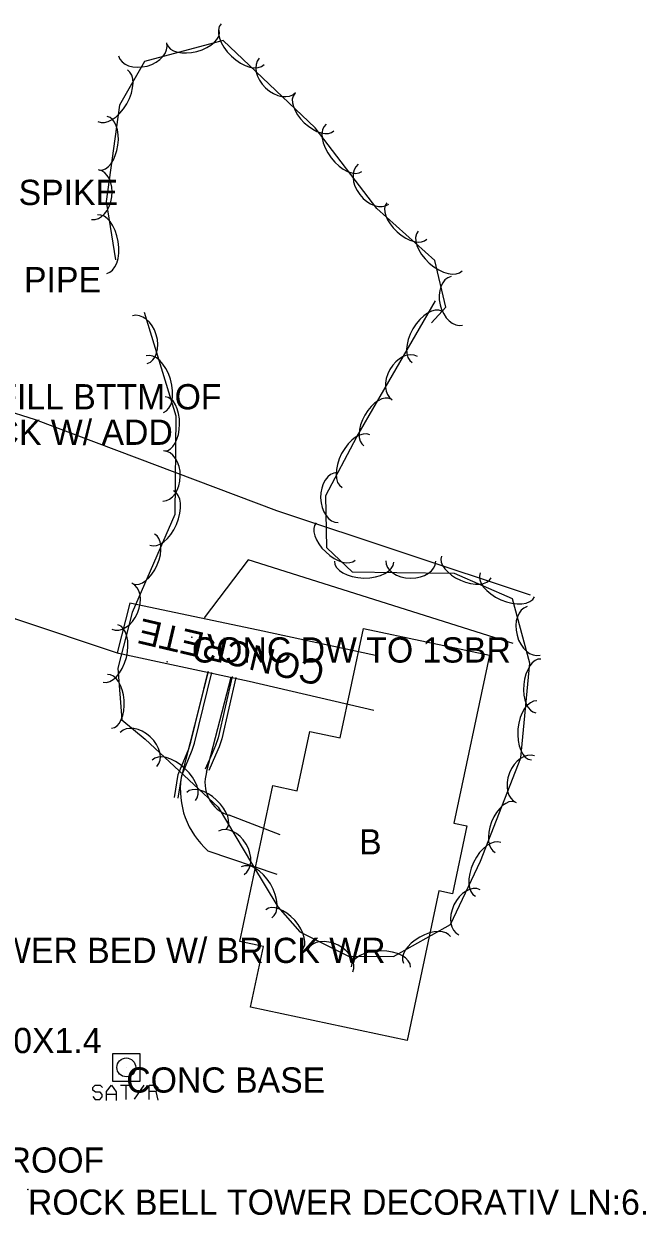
# Model space of a CAD drawing. Extents: x 954793 to 988390, y 1867850 to 1924428.
# Drawn here: x 961195.8 to 961319, y 1905785.4 to 1906021.4 of the extents above; entities that cross this region are included whole.
import ezdxf

# ---------------------------------------------------------------- set-up
doc = ezdxf.new("R2010")
doc.units = 0
for name, color, linetype in [('S_BUILDING', 7, 'Continuous'), ('S_BUILDING_ANNOT', 7, 'Continuous'), ('S_DRIVEWAY', 7, 'Continuous'), ('S_DRIVEWAY_ANNOT', 7, 'Continuous'), ('S_GRD_PT_SYM', 7, 'Continuous'), ('S_MISC_STRUCTURES_ANNOT', 7, 'Continuous'), ('S_MSC_PT_SYM', 7, 'Continuous'), ('S_PHOTO_IRON_PIN', 7, 'Continuous'), ('S_SATELLITE_RECEIVER', 7, 'Continuous'), ('S_SATELLITE_RECEIVER_ANNOT', 7, 'Continuous'), ('S_SECONDARY_CTL_ANNOT', 7, 'Continuous'), ('S_SIDE_DRAIN_ANNOT', 7, 'Continuous'), ('S_SIDEWALK', 7, 'Continuous'), ('S_SURVEY_TEXT_ANNOT', 7, 'Continuous'), ('S_TREE', 7, 'Continuous'), ('S_WATER_UTILITIES_ANNOT', 7, 'Continuous')]:
    doc.layers.add(name, color=color, linetype=linetype)

msp = doc.modelspace()

# ---------------------------------------------------------------- linework, layer by layer
at = {"layer": 'S_BUILDING'}
msp.add_lwpolyline([(961277.98, 1905849.64), (961271.68, 1905820.06), (961240.71, 1905826.65), (961243.26, 1905838.64), (961238.56, 1905839.64), (961245.13, 1905870.5), (961249.92, 1905869.47), (961252.43, 1905881.23), (961258.43, 1905879.96), (961263.04, 1905901.63), (961288, 1905896.31), (961280.92, 1905863.06), (961283.51, 1905862.51), (961280.64, 1905849.07)], close=True, dxfattribs=at)
at = {"layer": 'S_DRIVEWAY'}
for points in [[(961296.1, 1905908.22), (961245.91, 1905924.92), (961198.1, 1905942.95), (961151.44, 1905957.69), (961122.09, 1905969.17)], [(961117.43, 1905954.73), (961136.52, 1905950.69), (961174.2, 1905937.04), (961189.27, 1905931.84), (961190.7, 1905910.59), (961190.9, 1905906.51), (961191.87, 1905904.94), (961194.15, 1905903.56), (961214.46, 1905896.76)], [(961292.67, 1905898.66), (961240.24, 1905915.2), (961231.54, 1905903.74)], [(961265.41, 1905896.28), (961242.23, 1905901.3), (961216.78, 1905906.66), (961214.32, 1905896.78), (961240.4, 1905891.19), (961265.07, 1905885.47)]]:
    msp.add_lwpolyline(points, dxfattribs=at)
at = {"layer": 'S_GRD_PT_SYM'}
msp.add_lwpolyline([(961224.17, 1905895.04), (961224.17, 1905895.09), (961224.17, 1905895.04), (961224.12, 1905895.04), (961224.17, 1905895.04), (961224.17, 1905894.99), (961224.17, 1905895.04), (961224.22, 1905895.04)], dxfattribs=at)
at = {"layer": 'S_MSC_PT_SYM'}
for points in [[(961229.06, 1905899.87), (961229.06, 1905899.92), (961229.06, 1905899.87), (961229.01, 1905899.87), (961229.06, 1905899.87), (961229.06, 1905899.82), (961229.06, 1905899.87), (961229.11, 1905899.87)], [(961229.06, 1905899.87), (961229.06, 1905899.92), (961229.06, 1905899.87), (961229.01, 1905899.87), (961229.06, 1905899.87), (961229.06, 1905899.82), (961229.06, 1905899.87), (961229.11, 1905899.87)], [(961196.63, 1905790.52), (961196.63, 1905790.57), (961196.63, 1905790.52), (961196.58, 1905790.52), (961196.63, 1905790.52), (961196.63, 1905790.47), (961196.63, 1905790.52), (961196.68, 1905790.52)], [(961196.63, 1905790.52), (961196.63, 1905790.57), (961196.63, 1905790.52), (961196.58, 1905790.52), (961196.63, 1905790.52), (961196.63, 1905790.47), (961196.63, 1905790.52), (961196.68, 1905790.52)]]:
    msp.add_lwpolyline(points, close=True, dxfattribs=at)
for points in [[(961229.06, 1905899.87), (961229.06, 1905899.92), (961229.06, 1905899.87), (961229.01, 1905899.87), (961229.06, 1905899.87), (961229.06, 1905899.82), (961229.06, 1905899.87), (961229.11, 1905899.87)], [(961196.63, 1905790.52), (961196.63, 1905790.57), (961196.63, 1905790.52), (961196.58, 1905790.52), (961196.63, 1905790.52), (961196.63, 1905790.47), (961196.63, 1905790.52), (961196.68, 1905790.52)]]:
    msp.add_lwpolyline(points, dxfattribs=at)
at = {"layer": 'S_PHOTO_IRON_PIN'}
msp.add_line((961216.09, 1905814.71), (961216.09, 1905814.71), dxfattribs=at)
at = {"layer": 'S_SATELLITE_RECEIVER'}
for p, q in [((961209.47, 1905810.72), (961209.94, 1905811.19)), ((961209.47, 1905810.18), (961209.47, 1905810.72)), ((961209.94, 1905811.19), (961210.95, 1905811.19)), ((961210.95, 1905811.19), (961211.41, 1905810.72)), ((961212.19, 1905809.95), (961213.19, 1905811.19)), ((961213.19, 1905811.19), (961214.12, 1905809.87)), ((961214.98, 1905811.19), (961216.91, 1905811.19)), ((961215.98, 1905811.19), (961215.98, 1905808.32)), ((961217.69, 1905808.4), (961219.63, 1905811.19)), ((961220.63, 1905808.32), (961220.63, 1905811.19)), ((961220.63, 1905811.19), (961221.87, 1905811.19)), ((961221.87, 1905811.19), (961222.34, 1905810.72)), ((961222.34, 1905810.72), (961222.34, 1905810.33)), ((961210.02, 1905809.79), (961209.47, 1905810.18)), ((961209.47, 1905808.94), (961209.94, 1905808.32)), ((961209.94, 1905808.32), (961210.87, 1905808.32)), ((961210.95, 1905809.79), (961210.02, 1905809.79)), ((961210.87, 1905808.32), (961211.33, 1905808.86)), ((961211.33, 1905809.33), (961210.95, 1905809.79)), ((961211.33, 1905808.86), (961211.33, 1905809.33)), ((961212.19, 1905808.16), (961212.19, 1905809.95)), ((961214.05, 1905809.33), (961212.19, 1905809.33)), ((961214.12, 1905809.87), (961214.12, 1905808.16)), ((961221.95, 1905809.95), (961220.63, 1905809.95)), ((961222.34, 1905810.33), (961221.95, 1905809.95)), ((961221.95, 1905809.95), (961222.34, 1905808.24))]:
    msp.add_line(p, q, dxfattribs=at)
msp.add_lwpolyline([(961213.43, 1905811.94), (961213.43, 1905817.45), (961218.77, 1905817.45), (961218.77, 1905811.94)], close=True, dxfattribs=at)
msp.add_circle((961216.09, 1905814.71), 1.86, dxfattribs=at)
at = {"layer": 'S_SIDEWALK'}
for points in [[(961225.63, 1905868.14), (961226.35, 1905872.71), (961228.45, 1905877.81), (961228.86, 1905879.09), (961232.3, 1905893.1)], [(961226.37, 1905868.02), (961227.07, 1905872.5), (961229.16, 1905877.55), (961229.59, 1905878.88), (961233.03, 1905892.92)], [(961232.29, 1905893.07), (961226.95, 1905872.11)], [(961237.05, 1905892.1), (961234.26, 1905879.97), (961233.76, 1905878.43), (961233.09, 1905876.86), (961231.72, 1905873.79)], [(961232, 1905873.15), (961236.84, 1905892)], [(961237.78, 1905891.93), (961234.99, 1905879.77), (961234.47, 1905878.16), (961233.78, 1905876.56), (961232.41, 1905873.48)], [(961246.53, 1905860.76), (961236.47, 1905864.63)], [(961232.26, 1905857.58), (961245.87, 1905852.95)]]:
    msp.add_lwpolyline(points, dxfattribs=at)
msp.add_arc((961242.98, 1905869.73), 16.2, 171.5701, 228.5649, dxfattribs=at)
msp.add_ellipse((961238.34, 1905871.04), major_axis=(0.96, -6.61), ratio=0.999923, start_param=4.247433, end_param=5.854421, dxfattribs=at)
at = {"layer": 'S_TREE'}
for points in [[(961276.49, 1905962.13), (961279.37, 1905965.26), (961277.18, 1905974.46), (961265.68, 1905984.8), (961253.51, 1906000.75), (961235.24, 1906018.06), (961219.73, 1906013.92), (961214.76, 1906005.25), (961212.1, 1905986.15), (961213.94, 1905974.63)], [(961219.61, 1905964.23), (961225.9, 1905943.72), (961225.69, 1905924.19), (961217.26, 1905904.76), (961214.42, 1905893.76), (961215.18, 1905883.54), (961219.86, 1905879.68), (961234.31, 1905866.27), (961241.07, 1905854.81), (961246.08, 1905846.47), (961250.44, 1905841.56), (961260.08, 1905836.74), (961269, 1905836.69), (961280.26, 1905843.03), (961286.19, 1905855.57), (961294.18, 1905876), (961295.95, 1905894.74), (961292.57, 1905907.49), (961281.09, 1905912.51), (961269.65, 1905912.62), (961260.9, 1905912.76), (961255.79, 1905917.61), (961255.57, 1905927.92), (961261.72, 1905939.58), (961277.33, 1905966.48)]]:
    msp.add_lwpolyline(points, dxfattribs=at)
for centre, major_axis, ratio in [((961239.11, 1906017.31), (4.26, -4.04), 0.55008), ((961229.34, 1906018.69), (5.17, 1.38), 0.540699), ((961219.32, 1906016.28), (4.79, 1.28), 0.685311), ((961246.01, 1906011.14), (3.6, -3.41), 0.685311), ((961213.39, 1906007.13), (2.92, 5.09), 0.55008), ((961253.31, 1906003.86), (3.88, -3.68), 0.540699), ((961211.57, 1905997.7), (0.74, 5.3), 0.540699), ((961259.19, 1905996.8), (3.56, -4.66), 0.55008), ((961209.89, 1905987.53), (0.68, 4.91), 0.685311), ((961265.02, 1905989.6), (3.01, -3.94), 0.685311), ((961271.63, 1905982.31), (3.98, -3.58), 0.540699), ((961211.3, 1905977.72), (-0.93, 5.79), 0.55008), ((961278.22, 1905976.38), (4.36, -3.92), 0.55008), ((961281.52, 1905966.5), (1.15, -4.82), 0.685311), ((961218.78, 1905958.8), (-1.45, 4.74), 0.685311), ((961275.64, 1905959.35), (-2.94, -5.08), 0.55008), ((961221.75, 1905950.02), (-1.72, 5.61), 0.55008), ((961271.22, 1905951.21), (-2.49, -4.29), 0.685311), ((961223.76, 1905942.12), (0.06, 5.35), 0.540699), ((961265.82, 1905942.43), (-2.68, -4.62), 0.540699), ((961261.57, 1905934.75), (-2.74, -5.19), 0.55008), ((961223.39, 1905931.82), (0.05, 4.96), 0.685311), ((961257.96, 1905927.55), (0.1, -4.95), 0.685311), ((961223.08, 1905923.51), (2.33, 5.38), 0.55008), ((961257.55, 1905918.86), (3.87, -3.68), 0.540699), ((961219.56, 1905915.38), (2.13, 4.91), 0.540699), ((961263.16, 1905914.84), (5.87, -0.09), 0.55008), ((961272.41, 1905914.98), (4.96, -0.05), 0.685311), ((961283.41, 1905913.81), (4.9, -2.14), 0.540699), ((961291.53, 1905910.26), (5.38, -2.35), 0.55008), ((961215.22, 1905906.03), (1.97, 4.55), 0.685311), ((961296.72, 1905901.15), (1.27, -4.79), 0.685311), ((961212.98, 1905896.66), (1.47, 5.68), 0.55008), ((961297.66, 1905890.25), (-0.5, -5.32), 0.540699), ((961212.78, 1905887.2), (-0.4, 5.33), 0.540699), ((961296.83, 1905881.42), (-0.55, -5.84), 0.55008), ((961218.54, 1905877.66), (-3.63, 3.37), 0.685311), ((961225.5, 1905871.55), (-4.3, 3.99), 0.55008), ((961295.09, 1905871.77), (-1.81, -4.61), 0.685311), ((961232, 1905865.52), (-3.92, 3.64), 0.540699), ((961291.09, 1905862.27), (-1.95, -4.98), 0.540699), ((961236.89, 1905857.2), (-2.52, 4.27), 0.685311), ((961287.74, 1905853.9), (-2.51, -5.31), 0.55008), ((961241.87, 1905849.37), (-3.02, 5.03), 0.55008), ((961284.02, 1905845.42), (-2.12, -4.48), 0.685311), ((961247.29, 1905841.91), (-3.55, 4), 0.540699), ((961275.6, 1905837.98), (-4.66, -2.62), 0.540699), ((961256.49, 1905835.87), (-4.43, 2.22), 0.685311), ((961266.5, 1905834.59), (-5.87, 0.03), 0.55008)]:
    msp.add_ellipse(centre, major_axis=major_axis, ratio=ratio, start_param=3.141593, end_param=6.283185, dxfattribs=at)

# ---------------------------------------------------------------- texts
at = {"layer": 'S_BUILDING_ANNOT'}
msp.add_text('B', height=5, dxfattribs=at).set_placement((961262.18, 1905856.87))
at = {"layer": 'S_DRIVEWAY_ANNOT'}
msp.add_text('CONCRETE', height=5, rotation=166.7373, dxfattribs=at).set_placement((961255.7, 1905895.05))
at = {"layer": 'S_MISC_STRUCTURES_ANNOT'}
msp.add_text('IN GROUND ELECTRIC BOX 2.0X1.4', height=5, dxfattribs=at).set_placement((961097.13, 1905817.53))
at = {"layer": 'S_SATELLITE_RECEIVER_ANNOT'}
msp.add_text('CONC BASE', height=5, dxfattribs=at).set_placement((961216.09, 1905809.71))
at = {"layer": 'S_SECONDARY_CTL_ANNOT'}
msp.add_text('PD:8 SPK 8 SPIKE', height=5, dxfattribs=at).set_placement((961157.24, 1905985.47))
at = {"layer": 'S_SIDE_DRAIN_ANNOT'}
for s, p in [('CN:0%FILL BTTM OF PIPE', (961128.24, 1905968.19)), ('DI:24" TY:CMP CN:0%FILL BTTM OF', (961121.86, 1905945.01))]:
    msp.add_text(s, height=5, dxfattribs=at).set_placement(p)
at = {"layer": 'S_SURVEY_TEXT_ANNOT'}
for s, p in [('LARGE DECOR ROCK W/ ADD', (961129.46, 1905937.98)), ('CONC DW TO 1SBR', (961229.06, 1905894.87)), ('11.0 DI FLOWER BED W/ BRICK WR', (961154.48, 1905835.38)), ('ROCK BELL TOWER DECORATIV LN:6.', (961196.63, 1905785.52))]:
    msp.add_text(s, height=5, dxfattribs=at).set_placement(p)
at = {"layer": 'S_WATER_UTILITIES_ANNOT'}
msp.add_text('FREEZE PROOF', height=5, dxfattribs=at).set_placement((961159.71, 1905793.86))

doc.saveas('drawing.dxf')
